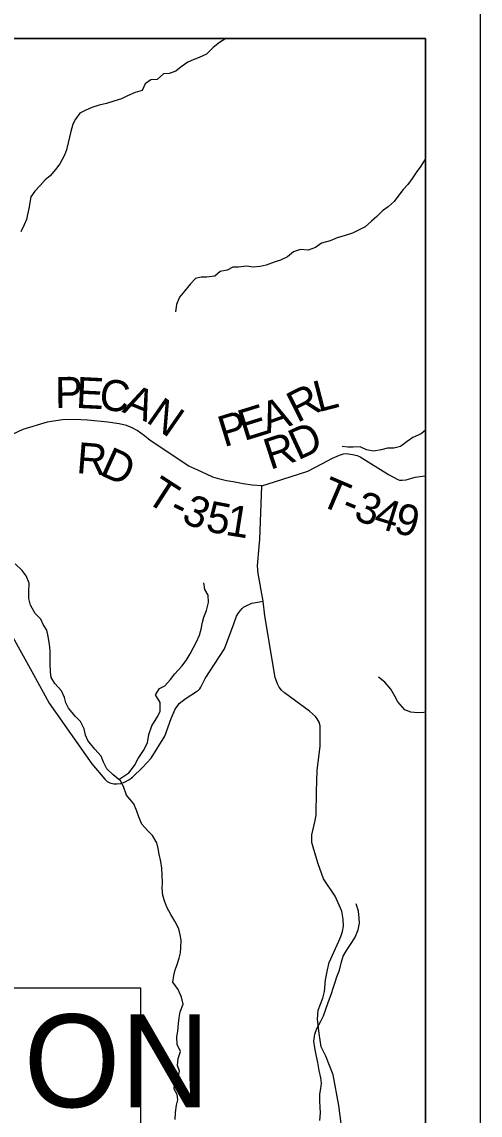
# Model space of a CAD drawing. Extents: x -20.5 to 34, y -66 to 23.9.
# Drawn here: x 8.16 to 9, y 18.93 to 20.931 of the extents above; entities that cross this region are included whole.
import ezdxf

# ---------------------------------------------------------------- set-up
doc = ezdxf.new("R2010")
doc.units = 0
for name, color, linetype in [('Default', 7, 'Continuous'), ('GM_X_County_Text', 7, 'Continuous'), ('GM_X_Minor_River_Text', 7, 'Continuous'), ('GM_X_Section_Text', 7, 'Continuous'), ('SH_Cut_Line', 7, 'Continuous'), ('SH_Data', 7, 'Continuous'), ('SH_Text', 7, 'Continuous')]:
    doc.layers.add(name, color=color, linetype=linetype)

msp = doc.modelspace()

# ---------------------------------------------------------------- linework, layer by layer
at = {"layer": 'Default'}
msp.add_lwpolyline([(2.1, 20.9), (8.9, 20.9), (8.9, 14.1), (2.1, 14.1)], close=True, dxfattribs=at)
msp.add_lwpolyline([(8.3774, 18.8452), (8.7292, 18.8379), (8.9, 18.8361), (8.9, 20.9), (2.1, 20.9), (2.1, 19.024), (2.1138, 19.0238), (2.8866, 19.0123), (2.9847, 19.0125), (3.3332, 19.0103), (5.1839, 18.9738), (5.2343, 18.9736), (5.2893, 18.9731), (5.9456, 18.969), (5.9451, 18.8918), (6.0429, 18.8899), (6.0928, 18.889), (6.2064, 18.8869)], dxfattribs=at)
at = {"layer": 'GM_X_County_Text'}
for points in [[(8.5999, 20.0812), (8.5825, 20.083), (8.5658, 20.0854), (8.5473, 20.0887), (8.5354, 20.0906), (8.5231, 20.0934), (8.51, 20.0973), (8.4985, 20.1029), (8.4827, 20.1099), (8.4664, 20.1174), (8.3955, 20.1647), (8.385, 20.1728), (8.3716, 20.1825), (8.3626, 20.1877), (8.3522, 20.1918), (8.3385, 20.1949), (8.318, 20.1979), (8.2806, 20.2019), (8.2569, 20.2026), (8.2349, 20.2025), (8.2064, 20.1981), (8.1622, 20.1843), (8.1324, 20.1704)], [(8.5999, 20.0812), (8.6367, 20.0932), (8.684, 20.1086), (8.7097, 20.1216), (8.7292, 20.1323), (8.7424, 20.1379), (8.7496, 20.1398), (8.7546, 20.1404), (8.766, 20.1391), (8.7746, 20.1369), (8.7802, 20.1344), (8.8322, 20.102), (8.8492, 20.0928), (8.8522, 20.092), (8.8571, 20.0917), (8.8644, 20.0924), (8.8811, 20.0973), (8.8985, 20.0999), (8.9, 20.1)], [(8.5952, 19.9702), (8.5964, 19.9831), (8.5999, 20.0812)], [(8.6026, 19.8707), (8.593, 19.921), (8.5922, 19.9353), (8.5952, 19.9702)], [(8.141, 19.8099), (8.1817, 19.7362), (8.2105, 19.684), (8.2888, 19.5726), (8.3125, 19.5444), (8.3165, 19.5405), (8.3215, 19.5382), (8.3288, 19.536), (8.3341, 19.5359), (8.3418, 19.5369), (8.3481, 19.5392), (8.356, 19.5432), (8.3628, 19.5482), (8.3816, 19.566), (8.3975, 19.5831), (8.4222, 19.6235), (8.4337, 19.6556), (8.4414, 19.6725), (8.446, 19.6797), (8.4488, 19.6829), (8.4538, 19.6872), (8.4612, 19.6926), (8.4804, 19.7048), (8.4842, 19.7075), (8.4864, 19.7101), (8.4882, 19.7129), (8.4963, 19.7287), (8.5313, 19.7833), (8.5487, 19.8289), (8.5538, 19.8427), (8.558, 19.8499), (8.5608, 19.8535), (8.5637, 19.8568), (8.5664, 19.8593), (8.5735, 19.8633), (8.5778, 19.8652), (8.5815, 19.8668), (8.6026, 19.8707)], [(8.7457, 18.9093), (8.741, 18.9471), (8.7307, 19.0033), (8.717, 19.0377), (8.7087, 19.0547), (8.7048, 19.0794), (8.7018, 19.1055), (8.7032, 19.1217), (8.7119, 19.1438), (8.7146, 19.1561), (8.7167, 19.1772), (8.7201, 19.1958), (8.7231, 19.209), (8.7409, 19.2484), (8.7445, 19.2564), (8.748, 19.2656), (8.7495, 19.2755), (8.7492, 19.2886), (8.7465, 19.3033), (8.7345, 19.3302), (8.7131, 19.3623), (8.7031, 19.3896), (8.695, 19.4159), (8.6918, 19.4285), (8.6914, 19.4427), (8.6977, 19.4692), (8.6998, 19.4794), (8.7002, 19.5219), (8.7016, 19.5602), (8.7069, 19.6053), (8.7069, 19.6337), (8.7067, 19.642), (8.7048, 19.6492), (8.7011, 19.6553), (8.6981, 19.6591), (8.6873, 19.6692), (8.6414, 19.7024), (8.6359, 19.7074), (8.6318, 19.7132), (8.6288, 19.7189), (8.6247, 19.731), (8.6054, 19.8434), (8.6026, 19.8707)]]:
    msp.add_lwpolyline(points, dxfattribs=at)
at = {"layer": 'GM_X_Minor_River_Text'}
for points in [[(8.5348, 20.9), (8.5321, 20.8987), (8.5223, 20.8928), (8.5107, 20.8835), (8.4984, 20.8716), (8.4852, 20.8653), (8.4739, 20.8609), (8.4641, 20.8566), (8.4521, 20.8481), (8.4423, 20.8407), (8.4299, 20.8359), (8.42, 20.8354), (8.4084, 20.8253), (8.3967, 20.8244), (8.3865, 20.817), (8.381, 20.8052), (8.3678, 20.8012), (8.3539, 20.7952), (8.3429, 20.7898), (8.3286, 20.7857), (8.3154, 20.7813), (8.3021, 20.7785), (8.2882, 20.7737), (8.2765, 20.7686), (8.2667, 20.7635), (8.2585, 20.7527), (8.2534, 20.7432), (8.2498, 20.7302), (8.2473, 20.7195), (8.2452, 20.7093), (8.242, 20.6967), (8.2384, 20.6868), (8.2299, 20.6707), (8.2221, 20.6603), (8.2124, 20.6488), (8.2027, 20.6414), (8.1937, 20.6314), (8.184, 20.621), (8.177, 20.6103), (8.1732, 20.5893), (8.1707, 20.5783), (8.169, 20.5688), (8.1646, 20.5592), (8.1583, 20.5462)], [(8.9, 20.6797), (8.8995, 20.6793), (8.891, 20.6663), (8.8828, 20.6547), (8.8754, 20.644), (8.8673, 20.6332), (8.8591, 20.6236), (8.8509, 20.6136), (8.8427, 20.6021), (8.8315, 20.5921), (8.821, 20.585), (8.8105, 20.5743), (8.8008, 20.5661), (8.7892, 20.5553), (8.7768, 20.5494), (8.7659, 20.5439), (8.7526, 20.5399), (8.7379, 20.5355), (8.7251, 20.53), (8.7096, 20.5256), (8.6983, 20.5174), (8.6847, 20.513), (8.6707, 20.5139), (8.6582, 20.5095), (8.647, 20.5006), (8.6342, 20.4947), (8.6244, 20.4912), (8.6081, 20.4856), (8.5968, 20.4827), (8.5839, 20.4818), (8.5717, 20.4835), (8.5573, 20.4817), (8.5471, 20.4816), (8.5365, 20.4765), (8.5237, 20.4736), (8.5136, 20.4655), (8.4995, 20.4637), (8.4889, 20.4632), (8.4787, 20.4607), (8.469, 20.4511), (8.4582, 20.4376), (8.4493, 20.4269), (8.4434, 20.4135), (8.4417, 20.4002)], [(8.9, 20.1835), (8.892, 20.1768), (8.8766, 20.1697), (8.8664, 20.1627), (8.854, 20.1534), (8.8419, 20.1506), (8.8302, 20.1504), (8.8188, 20.1475), (8.8044, 20.145), (8.7915, 20.1471), (8.7804, 20.1526), (8.7671, 20.1524), (8.7576, 20.1522), (8.747, 20.1532)], [(8.3518, 19.5152), (8.3466, 19.5313), (8.3411, 19.5415), (8.3273, 19.5526), (8.3157, 19.5634), (8.3098, 19.5759), (8.3054, 19.5868), (8.2942, 19.5995), (8.2814, 19.6152), (8.2771, 19.6254), (8.2746, 19.6367), (8.2679, 19.6499), (8.2583, 19.6596), (8.2459, 19.6746), (8.2411, 19.6844), (8.2387, 19.6942), (8.2332, 19.7066), (8.2208, 19.7197), (8.2138, 19.7306), (8.2125, 19.7412), (8.2122, 19.7564), (8.2124, 19.7693), (8.2122, 19.7795), (8.2108, 19.792), (8.2087, 19.8057), (8.2062, 19.8174), (8.1996, 19.8279), (8.1949, 19.8377), (8.1849, 19.8478), (8.1759, 19.8632), (8.173, 19.8753), (8.1728, 19.8874), (8.1737, 19.9034), (8.1681, 19.9165), (8.1608, 19.9267), (8.148, 19.939)], [(8.3378, 19.5441), (8.3564, 19.5565), (8.3668, 19.5696), (8.3735, 19.5822), (8.3831, 19.5968), (8.3904, 19.6109), (8.3932, 19.6261), (8.3983, 19.6422), (8.4097, 19.6598), (8.4138, 19.6693), (8.4135, 19.6849), (8.4053, 19.6992), (8.4123, 19.7107), (8.4221, 19.7154), (8.4325, 19.7273), (8.4403, 19.7377), (8.4534, 19.7516), (8.4612, 19.7619), (8.4686, 19.7738), (8.4745, 19.7857), (8.48, 19.796), (8.4855, 19.8079), (8.4887, 19.8189), (8.4911, 19.8318), (8.4936, 19.8414), (8.4984, 19.8536), (8.5023, 19.8677), (8.5017, 19.8813), (8.4955, 19.8915), (8.4937, 19.904)], [(8.9, 19.6674), (8.8971, 19.6666), (8.8854, 19.666), (8.8732, 19.6673), (8.8617, 19.6717), (8.8494, 19.6859), (8.8439, 19.6968), (8.8361, 19.7096), (8.8252, 19.7219), (8.8137, 19.7316)], [(8.4411, 18.9219), (8.4416, 18.9348), (8.4437, 18.9481), (8.4458, 18.958), (8.4449, 18.9675), (8.4391, 18.9773), (8.4397, 18.9868), (8.4467, 18.9994), (8.4492, 19.01), (8.4452, 19.0206), (8.4466, 19.0331), (8.4509, 19.0465), (8.4446, 19.0593), (8.4441, 19.0729), (8.4462, 19.0836), (8.4475, 19.0976), (8.4488, 19.1079), (8.4502, 19.1185), (8.4556, 19.133), (8.4528, 19.1459), (8.4469, 19.1595), (8.4372, 19.173), (8.4389, 19.1855), (8.4411, 19.1954), (8.4447, 19.2053), (8.4487, 19.2171), (8.4508, 19.227), (8.4518, 19.2365), (8.4523, 19.2498), (8.4503, 19.26), (8.4482, 19.271), (8.4404, 19.2845), (8.4334, 19.2969), (8.4257, 19.3101), (8.4225, 19.3203), (8.4185, 19.332), (8.4176, 19.3449), (8.4178, 19.3551), (8.4172, 19.3691), (8.4166, 19.382), (8.4149, 19.3941), (8.4117, 19.4074), (8.41, 19.418), (8.4076, 19.4282), (8.3998, 19.4413), (8.3902, 19.4507), (8.3802, 19.4623), (8.3755, 19.474), (8.3708, 19.486), (8.3656, 19.4992), (8.3518, 19.5152)], [(8.706, 18.9198), (8.7077, 18.9339), (8.7071, 18.9445), (8.7062, 18.9551), (8.706, 18.9684), (8.7081, 18.9786), (8.7095, 18.9881), (8.7082, 18.998), (8.7053, 19.0112), (8.7025, 19.0263), (8.6996, 19.0403), (8.6971, 19.0532), (8.6954, 19.0653), (8.6971, 19.0778), (8.7008, 19.0885), (8.7081, 19.1019), (8.7129, 19.1114), (8.7165, 19.1221), (8.7216, 19.1358), (8.7278, 19.1526), (8.7307, 19.1622), (8.7343, 19.1732), (8.7372, 19.1827), (8.7423, 19.1953), (8.7462, 19.2106), (8.7487, 19.2205), (8.7561, 19.2331), (8.7646, 19.2457), (8.7709, 19.2553), (8.7763, 19.2687), (8.7788, 19.2808), (8.7783, 19.2903), (8.7769, 19.3032), (8.773, 19.3164)]]:
    msp.add_lwpolyline(points, dxfattribs=at)
at = {"layer": 'SH_Cut_Line'}
msp.add_lwpolyline([(8.0662, 14.9881), (8.0784, 15.8902), (8.0825, 16.3121), (8.087, 16.6605), (8.0955, 17.3258), (8.2289, 17.3235), (8.271, 17.3227), (8.5216, 17.3182), (8.9, 17.3115), (8.9, 20.9), (2.1, 20.9), (2.1, 14.4131)], dxfattribs=at)
at = {"layer": 'SH_Data'}
for p, q in [((9, 21), (9, 14)), ((2.1, 20.9), (8.9, 20.9)), ((8.9, 20.9), (8.9, 14.1))]:
    msp.add_line(p, q, dxfattribs=at)
at = {"layer": 'SH_Text'}
msp.add_lwpolyline([(6.2064, 19.1628), (8.3774, 19.1628), (8.3774, 18.3792), (6.2064, 18.3792)], close=True, dxfattribs=at)

# ---------------------------------------------------------------- texts
at = {"layer": 'GM_X_Section_Text'}
for s, rotation, p in [('P', 0.7103, (8.2213, 20.2239)), ('E', 357.1575, (8.2587, 20.2243)), ('C', 352.2447, (8.2998, 20.2224)), ('L', 14.556, (8.7034, 20.2159)), ('A', 337.6108, (8.3424, 20.2171)), ('R', 26.7247, (8.6647, 20.1961)), ('N', 325.2041, (8.3858, 20.1996)), ('E', 17.2226, (8.5673, 20.1632)), ('A', 19.1856, (8.6099, 20.1764)), ('P', 17.2231, (8.5307, 20.1518)), ('D', 24.7431, (8.6661, 20.1276)), ('R', 18.0474, (8.6151, 20.1105)), ('R', 355.4091, (8.2592, 20.1049)), ('D', 335.6266, (8.3008, 20.1025)), ('T', 327.1396, (8.3843, 20.0543)), ('T', 336.9753, (8.7028, 20.0475)), ('3', 339.5586, (8.7661, 20.021)), ('3', 337.2544, (8.4507, 20.0161)), ('5', 349.1487, (8.4953, 19.9989)), ('-', 337.6362, (8.7426, 20.0306)), ('4', 342.8654, (8.8023, 20.0076)), ('9', 346.6439, (8.8397, 19.9963)), ('-', 334.6511, (8.4271, 20.0273)), ('1', 350.8559, (8.5315, 19.992))]:
    msp.add_text(s, height=0.0568, rotation=rotation, dxfattribs=at).set_placement(p)
at = {"layer": 'SH_Text'}
msp.add_text('PROJECT LOCATION ', height=0.17, dxfattribs=at).set_placement((6.2187, 18.9442))

doc.saveas('drawing.dxf')
